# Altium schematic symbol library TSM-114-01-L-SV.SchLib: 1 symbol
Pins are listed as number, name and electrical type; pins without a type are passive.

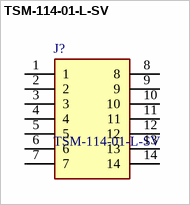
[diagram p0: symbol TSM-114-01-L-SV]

## TSM-114-01-L-SV
designator J?
Headers & Wire Housings .100" Surface Mount Terminal Strip; Manufacturer_Name: SAMTEC
footprint HUSRSP14W64P254_3556X254X838P
pins: 1, 2, 3, 4, 5, 6, 7, 8, 9, 10, 11, 12, 13, 14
